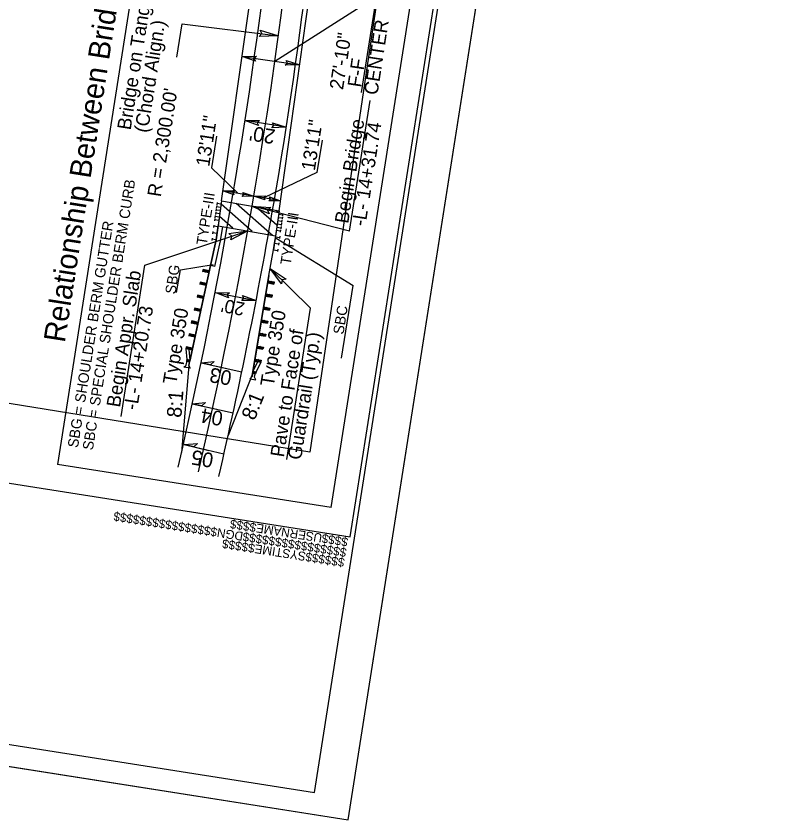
# Model space of a CAD drawing. Extents: x 1698669 to 1700017, y 707624 to 709955.
# Drawn here: x 1699557.3 to 1700017.4, y 707806.9 to 708286.4 of the extents above; entities that cross this region are included whole.
import ezdxf

# ---------------------------------------------------------------- set-up
doc = ezdxf.new("R2010")
doc.units = 0
for name, color, linetype in [('Prop Approach Slab', 7, 'Continuous'), ('Prop Approach Slab Hatching', 7, 'Continuous'), ('Prop Conc Shoulder Berm Gutter', 7, 'Continuous'), ('Prop Dimension', 7, 'Continuous'), ('Prop EOT', 7, 'Continuous'), ('Prop Guardrail', 7, 'Continuous'), ('Prop Guardrail Anchor Unit CELL', 7, 'Continuous'), ('Prop Horizontal Alignment', 7, 'Continuous'), ('Prop Paved Shoulder', 7, 'Continuous'), ('Prop Roadway Bridge', 7, 'Continuous'), ('Prop Structure Anchor Unit CELL', 7, 'Continuous'), ('Prop Superelevation  Arrow CELL', 7, 'Continuous'), ('Prop Superelevation Label', 7, 'Continuous'), ('Prop Terminator CELL', 7, 'Continuous'), ('Sheet Border Standard 30in CELL', 7, 'Continuous'), ('Sheet Clip Boundary CELL', 7, 'Continuous'), ('Sheet Cutting Line CELL', 7, 'Continuous'), ('Sheet Plot Border Inside CELL', 7, 'Continuous'), ('Sheet Plot Border Outside CELL', 7, 'Continuous')]:
    doc.layers.add(name, color=color, linetype=linetype)

msp = doc.modelspace()

# ---------------------------------------------------------------- linework, layer by layer
at = {"layer": 'Prop Approach Slab'}
for p, q in [((1699679.93, 708176.14), (1699677.84, 708161.38)), ((1699714.23, 708170.21), (1699712.11, 708155.27))]:
    msp.add_line(p, q, dxfattribs=at)
at = {"layer": 'Prop Approach Slab Hatching'}
for p, q in [((1699698.22, 708157.93), (1699679.65, 708174.2)), ((1699710.4, 708155.57), (1699688.64, 708174.64)), ((1699713.01, 708161.6), (1699700.46, 708172.59)), ((1699686.59, 708159.82), (1699678.61, 708166.81)), ((1699714.05, 708168.99), (1699712.27, 708170.55))]:
    msp.add_line(p, q, dxfattribs=at)
at = {"layer": 'Prop Conc Shoulder Berm Gutter'}
for p, q in [((1699676.64, 708152.94), (1699677.84, 708161.38)), ((1699673.25, 708137.63), (1699676.64, 708152.94)), ((1699712.11, 708155.27), (1699711.54, 708152.1))]:
    msp.add_line(p, q, dxfattribs=at)
at = {"layer": 'Prop Dimension'}
for p, q in [((1699711.72, 708259.43), (1699772.5, 708298.31)), ((1699763.45, 708240.74), (1699772.5, 708298.31)), ((1699653.27, 708261.86), (1699656.41, 708281.85)), ((1699656.41, 708281.85), (1699713.83, 708274.63)), ((1699692.13, 708262.21), (1699726.57, 708257.33)), ((1699756.26, 708158.05), (1699768.52, 708235.96)), ((1699718.52, 708220.12), (1699693.9, 708224.07)), ((1699676.86, 708214.75), (1699673.9, 708195.93)), ((1699739.89, 708212.46), (1699736.83, 708193.02)), ((1699673.9, 708195.93), (1699689.36, 708181)), ((1699736.83, 708193.02), (1699705.62, 708178.19)), ((1699699.16, 708179), (1699680.78, 708182.14)), ((1699715.09, 708176.28), (1699699.16, 708179)), ((1699756.26, 708158.05), (1699698.13, 708173)), ((1699634.18, 708137.9), (1699695.53, 708158.22)), ((1699712.42, 708153.9), (1699758.41, 708125.78)), ((1699619.98, 708047.64), (1699634.18, 708137.9)), ((1699655.45, 708135.05), (1699674.96, 708138.26)), ((1699653.09, 708121.57), (1699655.45, 708135.05)), ((1699733.01, 708112.23), (1699708.97, 708135.92)), ((1699751.57, 708082.38), (1699758.41, 708125.78)), ((1699676.1, 708121.61), (1699700.57, 708116.84)), ((1699718.81, 708021.97), (1699733.01, 708112.23))]:
    msp.add_line(p, q, dxfattribs=at)
at = {"layer": 'Prop EOT'}
for centre, radius, start, end in [((1696865.17, 708662.86), 2887.5, 350.26654, 356.20849), ((1696875.02, 708661), 2852.55, 346.9592, 353.61848), ((1696865.17, 708662.86), 2887.5, 346.96755, 350.26654)]:
    msp.add_arc(centre, radius, start, end, dxfattribs=at)
at = {"layer": 'Prop Guardrail'}
for p, q in [((1699676.64, 708152.94), (1699673.25, 708137.63)), ((1699708.2, 708131.57), (1699710.94, 708147.01))]:
    msp.add_line(p, q, dxfattribs=at)
at = {"layer": 'Prop Guardrail Anchor Unit CELL'}
for p, q in [((1699673.25, 708137.63), (1699660.93, 708080.51)), ((1699668.92, 708135.32), (1699668.65, 708134.1)), ((1699668.65, 708134.1), (1699670.75, 708134.92)), ((1699672.32, 708133.31), (1699668.65, 708134.1)), ((1699672.58, 708134.53), (1699668.92, 708135.32)), ((1699670.48, 708133.7), (1699668.92, 708135.32)), ((1699670.75, 708134.92), (1699670.48, 708133.7)), ((1699670.48, 708133.7), (1699672.58, 708134.53)), ((1699672.32, 708133.31), (1699670.48, 708133.7)), ((1699670.75, 708134.92), (1699672.32, 708133.31)), ((1699672.58, 708134.53), (1699672.32, 708133.31)), ((1699708.2, 708131.57), (1699698.54, 708073.94)), ((1699707.67, 708128.44), (1699707.46, 708127.21)), ((1699709.52, 708128.13), (1699707.46, 708127.21)), ((1699707.67, 708128.44), (1699711.37, 708127.82)), ((1699709.31, 708126.9), (1699707.67, 708128.44)), ((1699709.52, 708128.13), (1699709.31, 708126.9)), ((1699709.31, 708126.9), (1699711.37, 708127.82)), ((1699711.16, 708126.59), (1699709.52, 708128.13)), ((1699711.37, 708127.82), (1699711.16, 708126.59)), ((1699667.19, 708127.63), (1699666.93, 708126.41)), ((1699666.93, 708126.41), (1699669.06, 708127.23)), ((1699670.66, 708125.61), (1699666.93, 708126.41)), ((1699670.92, 708126.83), (1699667.19, 708127.63)), ((1699668.79, 708126.01), (1699667.19, 708127.63)), ((1699669.06, 708127.23), (1699668.79, 708126.01)), ((1699670.92, 708126.83), (1699668.79, 708126.01)), ((1699669.06, 708127.23), (1699670.66, 708125.61)), ((1699707.46, 708127.21), (1699711.16, 708126.59)), ((1699707.46, 708127.21), (1699709.31, 708126.9)), ((1699665.54, 708119.93), (1699665.27, 708118.71)), ((1699665.27, 708118.71), (1699667.4, 708119.53)), ((1699669, 708117.91), (1699665.27, 708118.71)), ((1699669.26, 708119.13), (1699665.54, 708119.93)), ((1699667.13, 708118.31), (1699665.54, 708119.93)), ((1699667.4, 708119.53), (1699667.13, 708118.31)), ((1699669.26, 708119.13), (1699667.13, 708118.31)), ((1699667.4, 708119.53), (1699669, 708117.91)), ((1699708.25, 708120.36), (1699706.16, 708119.44)), ((1699706.16, 708119.44), (1699709.93, 708118.81)), ((1699706.37, 708120.67), (1699710.13, 708120.04)), ((1699706.37, 708120.67), (1699708.04, 708119.12)), ((1699708.25, 708120.36), (1699708.04, 708119.12)), ((1699708.04, 708119.12), (1699710.13, 708120.04)), ((1699709.93, 708118.81), (1699708.25, 708120.36)), ((1699710.13, 708120.04), (1699709.93, 708118.81)), ((1699663.89, 708112.23), (1699663.63, 708111.01)), ((1699663.63, 708111.01), (1699665.75, 708111.83)), ((1699667.34, 708110.21), (1699663.63, 708111.01)), ((1699667.6, 708111.43), (1699663.89, 708112.23)), ((1699665.48, 708110.61), (1699663.89, 708112.23)), ((1699665.75, 708111.83), (1699665.48, 708110.61)), ((1699667.6, 708111.43), (1699665.48, 708110.61)), ((1699665.75, 708111.83), (1699667.34, 708110.21)), ((1699667.6, 708111.43), (1699667.34, 708110.21)), ((1699706.95, 708112.59), (1699704.86, 708111.67)), ((1699704.86, 708111.67), (1699708.62, 708111.04)), ((1699705.07, 708112.9), (1699708.82, 708112.27)), ((1699705.07, 708112.9), (1699706.74, 708111.36)), ((1699706.95, 708112.59), (1699706.74, 708111.36)), ((1699706.74, 708111.36), (1699708.82, 708112.27)), ((1699708.62, 708111.04), (1699706.95, 708112.59)), ((1699708.82, 708112.27), (1699708.62, 708111.04)), ((1699662.11, 708104.56), (1699661.84, 708103.33)), ((1699661.84, 708103.33), (1699664.02, 708104.14)), ((1699665.94, 708103.73), (1699662.11, 708104.56)), ((1699663.76, 708102.92), (1699662.11, 708104.56)), ((1699664.02, 708104.14), (1699663.76, 708102.92)), ((1699665.94, 708103.73), (1699663.76, 708102.92)), ((1699664.02, 708104.14), (1699665.68, 708102.51)), ((1699703.77, 708105.14), (1699703.56, 708103.9)), ((1699705.64, 708104.82), (1699703.56, 708103.9)), ((1699703.56, 708103.9), (1699707.3, 708103.28)), ((1699703.77, 708105.14), (1699707.51, 708104.51)), ((1699703.77, 708105.14), (1699705.43, 708103.59)), ((1699705.64, 708104.82), (1699705.43, 708103.59)), ((1699705.43, 708103.59), (1699707.51, 708104.51)), ((1699707.3, 708103.28), (1699705.64, 708104.82)), ((1699707.51, 708104.51), (1699707.3, 708103.28)), ((1699665.68, 708102.51), (1699661.84, 708103.33)), ((1699660.62, 708096.82), (1699660.35, 708095.6)), ((1699660.35, 708095.6), (1699662.45, 708096.43)), ((1699664.02, 708094.81), (1699660.35, 708095.6)), ((1699664.28, 708096.03), (1699660.62, 708096.82)), ((1699662.18, 708095.2), (1699660.62, 708096.82)), ((1699662.45, 708096.43), (1699662.18, 708095.2)), ((1699664.28, 708096.03), (1699662.18, 708095.2)), ((1699662.45, 708096.43), (1699664.02, 708094.81)), ((1699704.4, 708097.04), (1699702.26, 708096.13)), ((1699702.26, 708096.13), (1699706.13, 708095.49)), ((1699702.46, 708097.37), (1699706.33, 708096.72)), ((1699702.46, 708097.37), (1699704.19, 708095.81)), ((1699704.4, 708097.04), (1699704.19, 708095.81)), ((1699704.19, 708095.81), (1699706.33, 708096.72)), ((1699706.13, 708095.49), (1699704.4, 708097.04)), ((1699706.33, 708096.72), (1699706.13, 708095.49)), ((1699703.01, 708089.29), (1699700.95, 708088.37)), ((1699701.16, 708089.6), (1699704.86, 708088.98)), ((1699701.16, 708089.6), (1699702.8, 708088.06)), ((1699703.01, 708089.29), (1699702.8, 708088.06)), ((1699704.65, 708087.75), (1699703.01, 708089.29)), ((1699658.88, 708089.14), (1699658.61, 708087.91)), ((1699658.61, 708087.91), (1699660.75, 708088.73)), ((1699662.36, 708087.11), (1699658.61, 708087.91)), ((1699658.61, 708087.91), (1699659.23, 708081.51)), ((1699662.62, 708088.33), (1699658.88, 708089.14)), ((1699660.48, 708087.51), (1699658.88, 708089.14)), ((1699660.75, 708088.73), (1699660.48, 708087.51)), ((1699662.62, 708088.33), (1699660.48, 708087.51)), ((1699660.48, 708087.51), (1699661.07, 708081.12)), ((1699660.75, 708088.73), (1699662.36, 708087.11)), ((1699700.95, 708088.37), (1699704.65, 708087.75)), ((1699702.8, 708088.06), (1699704.86, 708088.98)), ((1699704.86, 708088.98), (1699704.65, 708087.75)), ((1699658.84, 708078.27), (1699659.34, 708080.79)), ((1699659.23, 708081.51), (1699658.97, 708080.29)), ((1699658.97, 708080.29), (1699661.07, 708081.12)), ((1699660.8, 708079.9), (1699658.97, 708080.29)), ((1699659.23, 708081.51), (1699659.1, 708080.9)), ((1699661.07, 708081.12), (1699659.23, 708081.51)), ((1699660.8, 708079.9), (1699659.23, 708081.51)), ((1699659.34, 708080.79), (1699660.08, 708080.64)), ((1699660.08, 708080.64), (1699660.83, 708080.49)), ((1699660.83, 708080.49), (1699660.34, 708077.98)), ((1699701.54, 708080.28), (1699698.64, 708074.56)), ((1699701.75, 708081.51), (1699699.65, 708080.6)), ((1699699.65, 708080.6), (1699703.43, 708079.96)), ((1699699.86, 708081.83), (1699703.64, 708081.2)), ((1699699.86, 708081.83), (1699701.54, 708080.28)), ((1699703.43, 708079.96), (1699700.49, 708074.25)), ((1699701.75, 708081.51), (1699701.54, 708080.28)), ((1699701.54, 708080.28), (1699703.64, 708081.2)), ((1699703.43, 708079.96), (1699701.75, 708081.51)), ((1699703.64, 708081.2), (1699703.43, 708079.96)), ((1699657.51, 708077.04), (1699658.84, 708078.27)), ((1699661.11, 708076.33), (1699657.51, 708077.04)), ((1699660.34, 708077.98), (1699661.11, 708076.33)), ((1699698.15, 708071.37), (1699696.83, 708070.12)), ((1699696.83, 708070.12), (1699700.44, 708069.45)), ((1699698.62, 708073.88), (1699698.15, 708071.37)), ((1699698.43, 708073.32), (1699700.49, 708074.25)), ((1699698.43, 708073.32), (1699700.28, 708073.01)), ((1699699.37, 708073.75), (1699698.62, 708073.88)), ((1699698.64, 708074.56), (1699700.49, 708074.25)), ((1699700.28, 708073.01), (1699698.64, 708074.56)), ((1699700.13, 708073.61), (1699699.37, 708073.75)), ((1699699.66, 708071.09), (1699700.13, 708073.61)), ((1699700.44, 708069.45), (1699699.66, 708071.09)), ((1699700.49, 708074.25), (1699700.28, 708073.01)), ((1699700.49, 708074.25), (1699700.39, 708073.63))]:
    msp.add_line(p, q, dxfattribs=at)
at = {"layer": 'Prop Horizontal Alignment'}
for p, q in [((1699660.94, 708520.75), (1699581.95, 708018.92)), ((1699745.36, 707993.2), (1699824.35, 708495.03)), ((1699745.36, 707993.2), (1699581.95, 708018.92))]:
    msp.add_line(p, q, dxfattribs=at)
msp.add_arc((1696865.17, 708662.86), 2875, 346.96755, 356.20849, dxfattribs=at)
at = {"layer": 'Prop Paved Shoulder'}
for p, q in [((1699679.39, 708152.33), (1699680.6, 708160.88)), ((1699676, 708137.03), (1699679.39, 708152.33)), ((1699710.94, 708147.01), (1699711.66, 708152.08)), ((1699708.2, 708131.57), (1699710.94, 708147.01)), ((1699660.34, 708077.98), (1699673.25, 708137.62)), ((1699676, 708137.03), (1699673.25, 708137.62)), ((1699698.39, 708073.04), (1699708.2, 708131.57)), ((1699660.34, 708077.98), (1699656.01, 708026.09)), ((1699698.39, 708073.04), (1699683.86, 708036.25))]:
    msp.add_line(p, q, dxfattribs=at)
at = {"layer": 'Prop Roadway Bridge'}
for p, q in [((1699679.93, 708176.14), (1699704.32, 708348.27)), ((1699714.23, 708170.21), (1699738.92, 708344.44)), ((1699679.93, 708176.14), (1699714.23, 708170.21)), ((1699677.84, 708161.38), (1699712.11, 708155.27))]:
    msp.add_line(p, q, dxfattribs=at)
at = {"layer": 'Prop Structure Anchor Unit CELL'}
for p, q in [((1699679.93, 708176.14), (1699676.64, 708152.94)), ((1699676.73, 708171.4), (1699676.53, 708169.98)), ((1699677.01, 708173.33), (1699676.8, 708171.92)), ((1699679.38, 708172.28), (1699676.9, 708172.63)), ((1699677.28, 708175.27), (1699677.08, 708173.85)), ((1699679.65, 708174.21), (1699677.18, 708174.56)), ((1699676.18, 708167.53), (1699675.98, 708166.12)), ((1699678.56, 708166.47), (1699676.08, 708166.82)), ((1699676.46, 708169.47), (1699676.26, 708168.05)), ((1699678.83, 708168.41), (1699676.36, 708168.76)), ((1699679.11, 708170.34), (1699676.63, 708170.69)), ((1699714.23, 708170.21), (1699710.94, 708147.01)), ((1699713.68, 708166.34), (1699716.15, 708165.99)), ((1699713.95, 708168.28), (1699716.43, 708167.93)), ((1699716.25, 708166.7), (1699716.05, 708165.28)), ((1699716.53, 708168.64), (1699716.33, 708167.22)), ((1699675.36, 708161.73), (1699675.16, 708160.31)), ((1699675.91, 708165.6), (1699675.71, 708164.18)), ((1699678.28, 708164.54), (1699675.81, 708164.89)), ((1699713.13, 708162.48), (1699715.61, 708162.13)), ((1699713.4, 708164.41), (1699715.88, 708164.06)), ((1699715.71, 708162.84), (1699715.5, 708161.42)), ((1699715.98, 708164.77), (1699715.78, 708163.35)), ((1699674.81, 708157.86), (1699674.61, 708156.45)), ((1699677.19, 708156.8), (1699674.71, 708157.16)), ((1699677.74, 708160.67), (1699675.26, 708161.02)), ((1699712.58, 708158.61), (1699715.06, 708158.26)), ((1699712.86, 708160.54), (1699715.33, 708160.19)), ((1699715.16, 708158.97), (1699714.96, 708157.55)), ((1699715.43, 708160.9), (1699715.23, 708159.48)), ((1699674.26, 708154), (1699674.06, 708152.58)), ((1699676.64, 708152.94), (1699674.16, 708153.29)), ((1699712.03, 708154.74), (1699714.51, 708154.39)), ((1699714.61, 708155.1), (1699714.41, 708153.68)), ((1699710.94, 708147.01), (1699713.41, 708146.66)), ((1699711.49, 708150.87), (1699713.96, 708150.52)), ((1699713.51, 708147.36), (1699713.31, 708145.95)), ((1699714.06, 708151.23), (1699713.86, 708149.81))]:
    msp.add_line(p, q, dxfattribs=at)
at = {"layer": 'Prop Superelevation  Arrow CELL'}
for p, q in [((1699667.68, 708079.56), (1699682.34, 708076.38)), ((1699662.48, 708055.11), (1699677.13, 708051.92)), ((1699657.69, 708030.8), (1699672.29, 708027.36))]:
    msp.add_line(p, q, dxfattribs=at)
for points in [[(1699667.68, 708079.56), (1699675.54, 708080.41), (1699673.33, 708078.33)], [(1699662.48, 708055.11), (1699670.34, 708055.96), (1699668.13, 708053.88)], [(1699657.69, 708030.8), (1699665.56, 708031.51), (1699663.31, 708029.47)]]:
    msp.add_lwpolyline(points, close=True, dxfattribs=at)
at = {"layer": 'Prop Superelevation Label'}
for p, q in [((1699667.68, 708079.56), (1699692.04, 708074.27)), ((1699662.48, 708055.11), (1699686.82, 708049.82)), ((1699657.69, 708030.8), (1699681.38, 708025.22))]:
    msp.add_line(p, q, dxfattribs=at)
at = {"layer": 'Prop Terminator CELL'}
for points in [[(1699702.94, 708278.04), (1699713.83, 708274.63), (1699702.36, 708274.14), (1699704.05, 708275.94)], [(1699700.28, 708259.6), (1699692.13, 708262.21), (1699700.74, 708262.52), (1699699.46, 708261.18)], [(1699718.42, 708259.96), (1699726.57, 708257.33), (1699717.96, 708257.04), (1699719.24, 708258.37)], [(1699701.97, 708221.19), (1699693.9, 708224.07), (1699702.52, 708224.1), (1699701.2, 708222.8)], [(1699710.35, 708222.66), (1699718.52, 708220.12), (1699709.92, 708219.74), (1699711.18, 708221.09)], [(1699687.32, 708179.85), (1699680.78, 708182.14), (1699687.76, 708182.2), (1699686.69, 708181.15)], [(1699692.59, 708181.23), (1699699.16, 708179), (1699692.18, 708178.87), (1699693.23, 708179.94)], [(1699705.71, 708176.73), (1699699.16, 708179), (1699706.14, 708179.09), (1699705.08, 708178.03)], [(1699708.55, 708178.59), (1699715.09, 708176.28), (1699708.11, 708176.24), (1699709.17, 708177.29)], [(1699708.28, 708168.4), (1699697.87, 708173.08), (1699709.32, 708172.19), (1699707.43, 708170.62)], [(1699684.23, 708156.63), (1699695.53, 708158.22), (1699685.37, 708152.86), (1699686.13, 708155.21)], [(1699715.72, 708126.71), (1699708.97, 708135.92), (1699718.5, 708129.5), (1699716.08, 708129.06)], [(1699684.06, 708118.44), (1699676.1, 708121.61), (1699684.72, 708121.32), (1699683.35, 708120.08)], [(1699692.5, 708119.69), (1699700.57, 708116.84), (1699691.95, 708116.79), (1699693.27, 708118.09)]]:
    msp.add_lwpolyline(points, close=True, dxfattribs=at)
at = {"layer": 'Sheet Border Standard 30in CELL'}
msp.add_lwpolyline([(1698952.79, 709620.82), (1698719.55, 708139.06), (1699756.78, 707975.8), (1699990.01, 709457.55)], close=True, dxfattribs=at)
at = {"layer": 'Sheet Clip Boundary CELL'}
msp.add_lwpolyline([(1698758.74, 708183.76), (1698948.48, 709389.16), (1699099.99, 709375.69), (1699125.7, 709552.26), (1699940.11, 709424.07), (1699732.55, 708026.32)], close=True, dxfattribs=at)
at = {"layer": 'Sheet Cutting Line CELL'}
for p, q in [((1699755.5, 707806.94), (1700017.35, 709470.46)), ((1698668.88, 707977.98), (1699755.5, 707806.94))]:
    msp.add_line(p, q, dxfattribs=at)
at = {"layer": 'Sheet Plot Border Inside CELL'}
msp.add_lwpolyline([(1698952.21, 709633.56), (1698693.08, 707987.33), (1699735.35, 707823.27), (1699994.48, 709469.5)], close=True, dxfattribs=at)
at = {"layer": 'Sheet Plot Border Outside CELL'}
msp.add_lwpolyline([(1698930.73, 709641.5), (1698668.88, 707977.98), (1699755.5, 707806.94), (1700017.35, 709470.46)], close=True, dxfattribs=at)

# ---------------------------------------------------------------- texts
at = {"layer": 'Prop Dimension'}
for s, height, rotation, p in [('Relationship Between Bridge and Pavement', 12.8174, 81.1024, (1699586.34, 708091.22)), ('Bridge on Tangent', 8.2031, 81.1024, (1699625.66, 708218.1)), ('(Chord Align.)', 8.2031, 81.1024, (1699635.93, 708216.49)), ('CENTER', 8.203, 81.3308, (1699772.95, 708238.98)), ('27\'-10"', 8.203, 81.3308, (1699752.39, 708242.12)), (' F-F', 8.203, 81.3308, (1699762.67, 708240.55)), ("R = 2,300.00' ", 8.2031, 81.1024, (1699643.65, 708178.2)), ('13\'11"', 8.203, 81.1024, (1699672.57, 708196.32)), ('13\'11"', 8.203, 81.1024, (1699735.57, 708193.82)), ('Begin Bridge', 8.2031, 81.1024, (1699755.49, 708162.33)), ("20'", 8.75, 171.0674, (1699712.44, 708218.6)), ('-L- 14+31.74', 8.2031, 81.1024, (1699765.77, 708160.72)), ('Begin Appr. Slab', 8.2031, 81.1024, (1699619.27, 708052.68)), ('-L- 14+20.73', 8.2031, 81.1024, (1699629.54, 708051.07)), ("20'", 7.998, 169.2597, (1699694.27, 708115.34)), ('Type 350', 8.203, 80.7477, (1699652.88, 708066.36)), ('Type 350', 8.203, 80.7477, (1699711.02, 708065.1)), ('Pave to Face of', 8.2031, 81.1024, (1699717.09, 708022.95)), ('Guardrail (Typ.)', 8.2031, 81.1024, (1699727.36, 708021.34)), ('8:1', 8.75, 85.2292, (1699655.88, 708046.63)), ('8:1', 8.75, 68.4512, (1699699.62, 708044.77))]:
    msp.add_text(s, height=height, rotation=rotation, dxfattribs=at).set_placement(p)
at = {"layer": 'Prop Structure Anchor Unit CELL'}
for s, p in [('SBC = SPECIAL SHOULDER BERM CURB', (1699603.09, 708027.18)), ('TYPE-III', (1699671.03, 708149.52)), ('TYPE-III', (1699721.1, 708137.62)), ('SBG = SHOULDER BERM GUTTER', (1699594.19, 708028.59)), ('SBG', (1699652.37, 708120.22)), ('SBC', (1699752.65, 708096.22))]:
    msp.add_text(s, height=6.25, rotation=81.0546, dxfattribs=at).set_placement(p)
at = {"layer": 'Prop Superelevation Label'}
for s, p in [('03', (1699686.48, 708074.57)), ('04', (1699681.27, 708050.41)), ('05', (1699675.6, 708025.48))]:
    msp.add_text(s, height=8.75, rotation=170.1291, dxfattribs=at).set_placement(p)
at = {"layer": 'Sheet Border Standard 30in CELL'}
for s, p in [('$$$$$$$$$$$$$$$$DGN$$$$$$$$$$$$$$$$', (1699754.82, 707968.87)), ('$$$$USERNAME$$$$', (1699755.7, 707975.11)), ('$$$$$$SYSTIME$$$$$', (1699753.69, 707962.92))]:
    msp.add_text(s, height=5.25, rotation=171.0546, dxfattribs=at).set_placement(p)

doc.saveas('drawing.dxf')
